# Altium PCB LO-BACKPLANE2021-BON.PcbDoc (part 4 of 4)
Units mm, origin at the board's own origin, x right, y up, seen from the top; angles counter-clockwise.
Board outline 469.9 x 101.6 mm, 4 copper layers (1, Signal Layer 1, Signal Layer 2, 4), stack 1.53 mm thick; 160 components, 92 nets, 524 pads, 8354 vias.
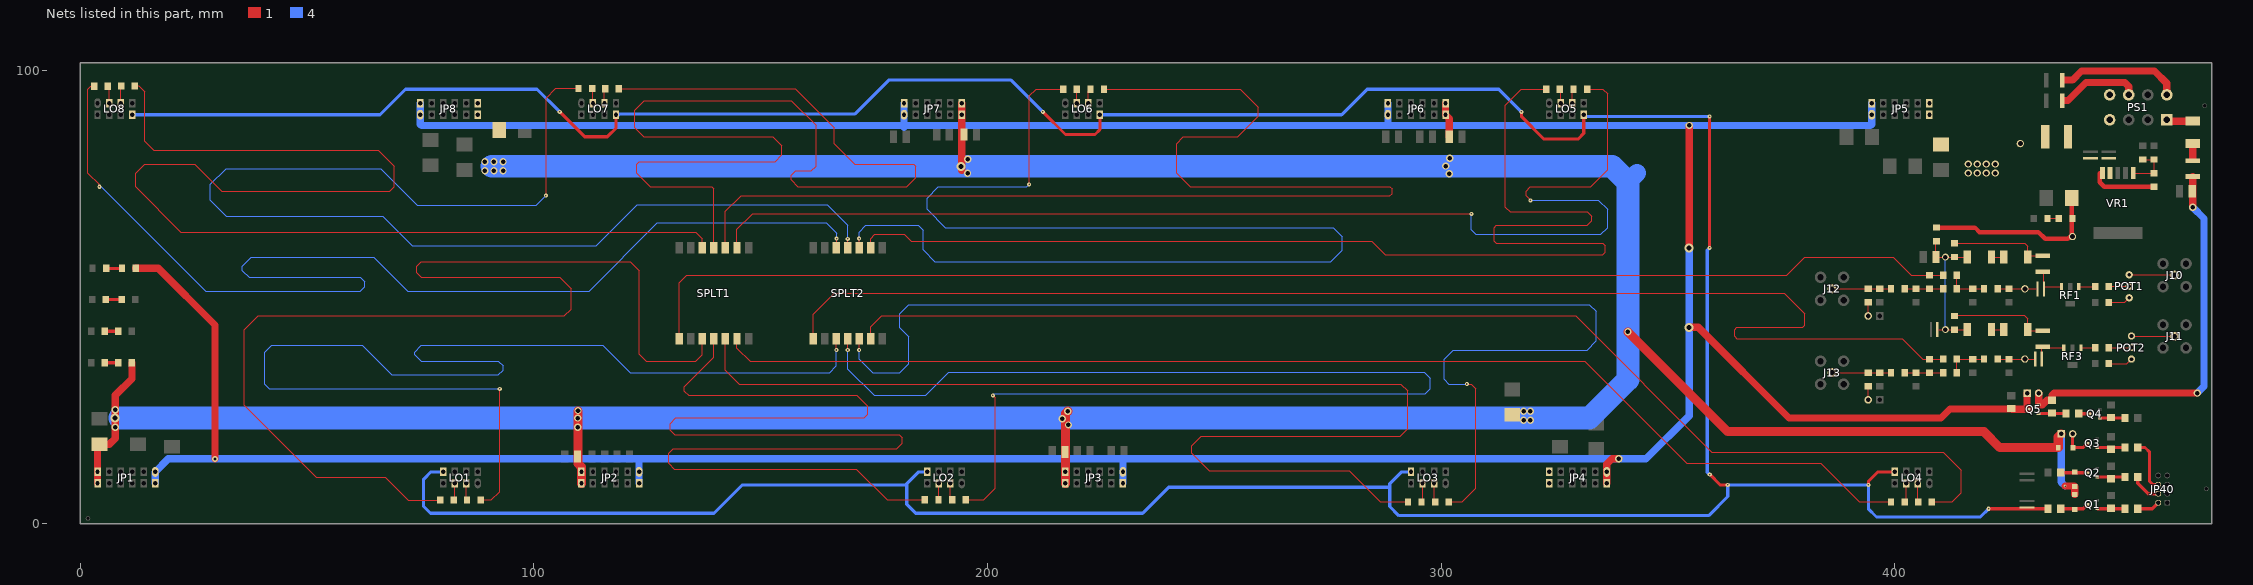
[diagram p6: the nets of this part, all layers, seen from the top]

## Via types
v1: diameter 0.9, hole 0.35, 1 to 4, 7972 vias
v2: diameter 0.7, hole 0.3, 1 to 4, 287 vias
v3: diameter 1.6, hole 1, 1 to 4, 60 vias
v4: diameter 0.762, hole 0.508, 1 to 4, 12 vias
v5: diameter 5.08, hole 3.85, 1 to 4, 12 vias
v6: diameter 2, hole 1.1, 1 to 4, 10 vias
v7: diameter 1.27, hole 0.7, 1 to 4, 1 vias

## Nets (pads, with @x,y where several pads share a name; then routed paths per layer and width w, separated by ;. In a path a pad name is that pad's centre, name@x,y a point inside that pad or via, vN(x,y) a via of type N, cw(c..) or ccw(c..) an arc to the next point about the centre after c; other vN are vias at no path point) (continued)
HFGAIN1: JP40.4 R72.1 | length 6.8
  1 w0.7: R72.1@453.6,10.3 453.6,8.9 455.88,6.62 JP40.4@458.105,6.62
I1: LO1.5 R18.2 | length 3.7
  1 w0.185: R18.2@82.369,5.23 82.55,5.411 LO1.5@82.55,8.89
I2: LO2.5 R17.2 | length 3.6
  1 w0.185: R17.2@189.2,5.3 189.23,5.33 LO2.5@189.23,8.89
I3: LO3.5 R16.2 | length 4.2
  1 w0.185: R16.2@295.7,4.8 295.91,5.01 LO3.5@295.91,8.89
I4: LO4.5 R15.2 | length 4.3
  1 w0.185: R15.2@402.2,4.8 402.59,5.19 LO4.5@402.59,8.89
I5: LO5.5 R14.2 | length 3.2
  1 w0.185: LO5.5@328.93,92.71 328.93,95.53 R14.2@329.2,95.8
I6: LO6.5 R13.2 | length 3.3
  1 w0.185: LO6.5@222.25,92.71 222.25,95.35 R13.2@222.7,95.8
I7: LO7.5 R12.2 | length 3.2
  1 w0.185: LO7.5@115.57,92.71 115.57,95.707 R12.2@115.744,95.881
I8: LO8.5 R11.2 | length 3.9
  1 w0.185: LO8.5@8.89,92.71 8.89,96.413 R11.2@9.004,96.527
I-BUS: C2.1 R20.1 R22.1 TP1.1 | length 8.5
  1 w0.185: R22.1@422.7,51.8 431.2,51.8
LFGAIN: C7.1 L1.1 LO1.8 LO2.8 LO3.8 LO4.8 LO5.8 LO6.8 LO7.8 LO8.8 | length 882.4
  1 w0.7: v1(105.7,90.8) 111.2,85.3 116.2,85.3 118.11,87.21 LO7.8@118.11,90.17 ; v1(212.2,90.8) 217.2,85.8 223.7,85.8 224.79,86.89 LO6.8@224.79,90.17 ; v1(317.7,90.8) 317.7,89.8 322.7,84.8 330.2,84.8 331.47,86.07 LO5.8@331.47,90.17 ; v1@359.199,10.877 361.526,8.55 v1(363.2,8.55) ; v1(359.2,60.8) v1(359.2,89.8) ; v1(394.2,8.55) 394.2,9.3 396.33,11.43 LO4.8@400.05,11.43 ; v1(420.7,3.3) L1.1@433.8,3.3
  4 w0.7: LO8.8@11.43,90.17 66.07,90.17 71.7,95.8 100.7,95.8 v1(105.7,90.8) ; LO1.8@80.01,11.43 77.33,11.43 75.7,9.8 75.7,3.8 77.2,2.3 139.7,2.3 145.95,8.55 182.2,8.55 ; LO7.8@118.11,90.17 118.7,90.17 118.83,90.3 170.7,90.3 178.2,97.8 205.2,97.8 v1(212.2,90.8) ; LO2.8@186.69,11.43 184.83,11.43 182.2,8.8 182.2,8.55 ; LO6.8@224.79,90.17 278.07,90.17 283.7,95.8 312.7,95.8 v1(317.7,90.8) ; LO3.8@293.37,11.43 291.33,11.43 288.7,8.8 288.7,8.05 ; LO5.8@331.47,90.17 331.84,89.8 v1(359.2,89.8) ; v1(359.2,60.8) 358.7,60.3 358.7,11.349 v1(359.226,10.822) ; v1(420.7,3.3) 418.892,1.492 396.008,1.492 394.2,3.3 v1(394.2,8.55) v1(363.2,8.55) 363.2,6.014 358.986,1.8 290.7,1.8 288.7,3.8 288.7,8.05 ; 182.2,8.55 182.2,4.3 184.2,2.3 234.2,2.3 239.95,8.05 288.7,8.05
LFGAIN1: JP40.2 R70.2 | length 4.6
  1 w0.7: R70.2@454.1,3.3 456.785,3.3 JP40.2@458.105,4.62
LOI1+: J10.1 POT1.3 | length 9.9
  1 w0.185: POT1.3@451.7,54.88 J10.1@461.62,54.88
LOI2: C1.2 POT1.2 | length 4.5
  1 w0.185: C1.2@447.2,52.3 447.24,52.34 POT1.2@451.7,52.34
LOI3: C1.1 RF1.1 | length 3.6
  1 w0.185: RF1.1@440.605,52.3 C1.1@444.2,52.3
LOI4: C2.2 L2.1 RF1.3 | length 6.9
  1 w0.185: L2.1@432.9,55.3 432.9,52.3 RF1.3@436.795,52.3
LOQ1+: J11.1 POT2.3 | length 9.5
  1 w0.185: POT2.3@452.2,41.38 452.28,41.3 J11.1@461.7,41.3
LOQ2: C3.2 POT2.2 | length 5
  1 w0.185: C3.2@447.2,38.8 447.24,38.84 POT2.2@452.2,38.84
LOQ3: C3.1 RF3.1 | length 3.1
  1 w0.185: RF3.1@441.105,38.8 C3.1@444.2,38.8
LOQ4: C4.2 L4.1 RF3.3 | length 9.2
  1 w0.185: C4.2@432.45,34.8 432.45,39.05 432.95,38.8 RF3.3@437.295,38.8
LOQ6: R54.2 R55.1 | length 2.7
  1 w0.185: R54.2@421.35,42.8 R55.1@424.05,42.8
NetC5_1: C5.1 C6.1 R44.1 R54.1 R91.2 R93.1 R94.1 | length 32.8
  1 w0.185: R91.2@409.2,62.3 409.1,62.2 C5.1@409.1,58.8 v3(411.2,58.8) R93.1@413.2,58.8 R44.1@416.05,58.8 ; 409.7,42.8 v3(411.2,42.8) R94.1@413.2,42.8 R54.1@416.05,42.8
  4 w0.185: v3(411.2,42.8) v3(411.2,58.8)
NetD1_A: D1.A L1.2 Q1.3 | length 6.3
  1 w0.7: L1.2@436.6,3.3 441.589,3.3 Q1.3@442.541,4.252
NetD2_A: D2.A L21.2 Q2.3 | length 6
  1 w0.185: L21.2@436.6,11.3 L21.2@436.648,11.252
  1 w0.7: L21.2@436.648,11.252 Q2.3@442.541,11.252
NetD103_A: D103.A JP13.2 Q3.3 | length 6.6
  1 w0.185: D103.A@439.24,16.895 D103.A@439.335,16.8
  1 w0.7: D103.A@439.24,16.895 JP13.2@439.24,19.8 ; D103.A@439.335,16.8 441.589,16.8 Q3.3@442.541,17.752
NetF1_1: F1.1 L13.2 | length 3.6
  1 w1.6: L13.2@465.7,80.3 F1.1@465.7,83.85
NetJ12_1: J12.1 R7.1 R61.1 R62.2 | length 13
  1 w0.185: J12.1@386.2,51.8 R7.1@394.2,51.8 R61.1@396.7,51.8 R62.2@399.2,51.8
NetJ13_1: J13.1 R8.1 R64.1 R65.2 | length 13
  1 w0.185: J13.1@386.2,33.3 R8.1@394.2,33.3 R64.1@396.7,33.3 R65.2@399.2,33.3
NetJP10_2: JP10.2 R7.2 | length 3
  1 w0.185: JP10.2@394.16,45.8 394.2,45.84 R7.2@394.2,48.8
NetJP11_2: JP11.2 R8.2 | length 3
  1 w0.185: JP11.2@394.2,27.34 R8.2@394.2,30.3
NetJP40_6: JP40.6 R74.1 | length 11.7
  1 w0.7: R74.1@453.6,16.8 455.2,16.8 456.2,15.8 456.2,9.3 456.88,8.62 JP40.6@458.105,8.62
NetL2_2: L2.2 R45.2 R93.2 | length 22.2
  1 w0.185: R93.2@413.2,61.8 428.7,61.8 429.35,61.15 R45.2@429.35,58.8 429.6,59.05 L2.2@432.7,59.05
NetL4_2: L4.2 R55.2 R94.2 | length 22.3
  1 w0.185: R94.2@413.2,45.8 413.325,45.925 428.575,45.925 429.35,45.15 R55.2@429.35,42.8 429.6,42.55 L4.2@432.7,42.55
NetL10_2: L10.2 PS1.4 PS1.8
NetL11_2: L11.2 PS1.7 | length 18.3
  1 w1.6: L11.2@437.2,93.3 438.2,93.3 442.2,97.3 450.7,97.3 451.6,96.4 PS1.7@451.6,94.55
NetL12_2: L12.2 PS1.5 | length 27.3
  1 w1.6: L12.2@437.2,97.8 439.2,97.8 441.2,99.8 457.3,99.8 460,97.1 PS1.5@460,94.55
NetLED1_A: LED1.A R92.2 | length 2.5
  1 w0.185: LED1.A@433.7,67.3 R92.2@436.2,67.3
NetLED80_A: LED80.A R80.1 | length 3
  1 w0.7: LED80.A@5.386,35.498 R80.1@8.386,35.498
NetLED81_A: LED81.A R81.1 | length 3
  1 w0.7: LED81.A@5.386,42.428 R81.1@8.386,42.428
NetLED82_K: LED82.K R82.1 | length 3.5
  1 w0.7: LED82.K@5.631,49.411 R82.1@9.131,49.411
NetLED83_A: LED83.A R83.1 | length 3.5
  1 w0.7: LED83.A@5.7,56.3 R83.1@9.2,56.3
NetPOT1_1: POT1.1 R42.1 | length 4.9
  1 w0.185: R42.1@447.2,48.8 450.7,48.8 POT1.1@451.7,49.8
NetPOT2_1: POT2.1 R52.1 | length 5.4
  1 w0.185: R52.1@447.2,35.3 451.2,35.3 POT2.1@452.2,36.3
NetQ3_1: Q3.1 R74.2 R75.1 | length 6.1
  1 w0.7: Q3.1@444.7,16.8 R74.2@450.8,16.8
NetQ4_1: Q4.1 R58.2 R59.1 | length 5.6
  1 w0.7: Q4.1@445.2,23.3 R58.2@450.8,23.3
NetQ4_3: Q4.3 R57.2 | length 2.5
  1 w0.185: R57.2@440.6,24.3 R57.2@440.648,24.252
  1 w0.7: R57.2@440.648,24.252 Q4.3@443.041,24.252
NetQ5_1: Q5.1 R56.2 R57.1 | length 6.1
  1 w0.7: Q5.1@431.7,24.3 R57.1@437.8,24.3
NetR1_1: R1.1 R2.1 R21.1 R22.2 | length 9
  1 w0.185: R1.1@413.7,54.8 R2.1@413.7,51.8 R22.2@419.7,51.8
NetR1_2: R1.2 R3.1 SPLT1.1 | length 295
  1 w0.185: SPLT1.1@132.08,40.765 132.08,53.18 133.7,54.8 376.2,54.8 380.2,58.8 399.7,58.8 403.7,54.8 R1.2@410.7,54.8
NetR2_2: R2.2 R3.2 R60.1 R62.1 | length 8.5
  1 w0.185: R62.1@402.2,51.8 R60.1@404.7,51.8 R3.2@407.7,51.8 R2.2@410.7,51.8
NetR4_1: R4.1 R5.1 R24.1 R25.2 | length 9
  1 w0.185: R5.1@413.7,33.3 R4.1@413.7,36.3 R24.1@417.2,36.3 R25.2@419.7,36.3
NetR4_2: R4.2 R6.1 SPLT2.1 | length 295.8
  1 w0.185: SPLT2.1@161.58,40.765 161.58,46.18 166.2,50.8 375.7,50.8 380.2,46.3 380.2,43.8 379.7,43.3 365.2,43.3 364.7,42.8 364.7,41.3 365.2,40.8 401.7,40.8 406.2,36.3 R6.1@407.7,36.3 R4.2@410.7,36.3
NetR5_2: R5.2 R6.2 R63.1 R65.1 | length 8.5
  1 w0.185: R65.1@402.2,33.3 R63.1@404.7,33.3 R5.2@410.7,33.3
NetR11_1: R11.1 SPLT1.12 | length 270.8
  1 w0.185: R11.1@12.004,96.527 12.838,96.527 14.178,95.186 14.178,84.322 16.2,82.3 65.7,82.3 69.2,78.8 69.2,74.3 68.2,73.3 31.2,73.3 25.2,79.3 14.2,79.3 12.2,77.3 12.2,74.3 22.2,64.3 135.7,64.3 137.16,62.84 SPLT1.12@137.16,60.835
NetR12_1: R12.1 SPLT1.11 | length 271.8
  1 w0.185: R12.1@118.744,95.881 157.619,95.881 166.2,87.3 166.2,83.8 170.7,79.3 183.7,79.3 184.2,78.8 184.2,76.3 182.2,74.3 158.2,74.3 156.7,75.8 156.7,76.8 157.7,77.8 161.2,77.8 162.2,78.8 162.2,87.8 156.7,93.3 124.328,93.3 122.2,91.172 122.2,87.3 124.2,85.3 152.7,85.3 154.7,83.3 154.7,81.3 153.2,79.8 123.2,79.8 122.7,79.3 122.7,77.3 125.7,74.3 139.2,74.3 139.7,73.8 SPLT1.11@139.7,60.835
NetR13_1: R13.1 SPLT1.10 | length 271.2
  1 w0.185: SPLT1.10@142.24,60.835 142.24,68.84 145.7,72.3 288.7,72.3 289.2,72.8 289.2,73.8 288.7,74.3 244.7,74.3 241.7,77.3 241.7,83.8 243.2,85.3 255.2,85.3 259.7,89.8 259.7,91.8 255.7,95.8 R13.1@225.7,95.8
NetR14_1: R14.1 SPLT1.9 | length 267.8
  1 w0.185: SPLT1.9@144.78,60.835 144.78,64.88 148.2,68.3 v1(306.7,68.3) ; v1@319.747,71.347 318.738,72.357 318.738,73.338 319.7,74.3 333.01,74.3 336.7,77.99 336.7,94.8 335.7,95.8 R14.1@332.2,95.8
  4 w0.185: v1(306.7,68.3) 306.7,64.8 307.7,63.8 335.2,63.8 336.7,65.3 336.7,69.3 334.7,71.3 v1(319.7,71.3)
NetR15_1: R15.1 SPLT1.6 | length 270.5
  1 w0.185: SPLT1.6@144.78,40.765 144.78,38.72 147.7,35.8 331.7,35.8 354.2,13.3 383.7,13.3 392.2,4.8 R15.1@399.2,4.8
NetR16_1: R16.1 SPLT1.5 | length 270.5
  1 w0.185: SPLT1.5@142.24,40.765 142.24,33.8 145.28,30.76 291.142,30.76 292.628,29.273 292.628,20.928 291.005,19.305 247.14,19.305 245.027,17.192 245.027,15.516 248.867,11.675 279.764,11.675 286.639,4.8 R16.1@292.7,4.8
NetR17_1: R17.1 SPLT1.4 | length 271.2
  1 w0.185: SPLT1.4@139.7,40.765 139.7,36.676 133.178,30.154 133.178,29.229 134.107,28.3 171.192,28.3 173.553,25.939 173.553,24.09 172.792,23.329 131.329,23.329 130.051,22.051 130.051,20.637 131.03,19.659 180.595,19.659 181.248,19.006 181.248,17.755 180.051,16.559 130.731,16.559 129.697,15.526 129.697,13.351 131.002,12.046 171.106,12.046 177.852,5.3 R17.1@186.2,5.3
NetR18_1: R18.1 SPLT1.3 | length 271
  1 w0.185: R18.1@79.096,5.23 72.27,5.23 67.2,10.3 51.997,10.3 36.167,26.13 36.167,42.769 39.198,45.8 106.7,45.8 108.2,47.3 108.2,51.8 105.7,54.3 75.2,54.3 74.2,55.3 74.2,56.8 75.2,57.8 121.2,57.8 123.229,55.771 123.229,37.329 124.758,35.8 135.7,35.8 137.16,37.26 SPLT1.3@137.16,40.765
NetR31_1: R31.1 SPLT2.12 | length 267.9
  1 w0.185: 1.664,78.3 1.664,95.782 2.31,96.428 R31.1@3.045,96.428 ; 1.7,78.3 1.7,77.3 4.2,74.8 v1@4.2,74.378 ; SPLT2.12@166.728,60.903 v1(166.728,62.859)
  4 w0.185: v1(4.2,74.3) 4.624,74.3 27.624,51.3 61.7,51.3 62.7,52.3 62.7,53.3 61.7,54.3 37.2,54.3 35.7,55.8 35.7,56.8 37.7,58.8 64.7,58.8 72.2,51.3 112.2,51.3 127.235,66.335 164.469,66.335 166.728,64.075 v1(166.728,62.859)
NetR32_1: R32.1 SPLT2.11 | length 267.8
  1 w0.185: v1@102.7,72.351 102.7,93.8 104.856,95.956 R32.1@109.835,95.956 ; SPLT2.11@169.2,60.835 v1(169.2,62.8)
  4 w0.185: v1(102.644,72.351) 100.524,70.23 74.27,70.23 66.2,78.3 32.2,78.3 28.7,74.8 28.7,71.3 32.2,67.8 66.7,67.8 73.188,61.312 113.765,61.312 122.753,70.3 164.7,70.3 169.2,65.8 v1(169.2,62.8)
NetR33_1: R33.1 SPLT2.10 | length 268.8
  1 w0.185: v1(171.7,62.84) 171.7,63.3 ; SPLT2.10@171.74,60.835 v1@171.74,62.84 ; v1(209.2,74.8) 209.2,94.3 210.7,95.8 R33.1@216.7,95.8
  4 w0.185: v1@171.7,62.8 v1(171.7,62.84) 171.7,64.3 173.2,65.8 184.753,65.8 185.815,64.738 185.815,60.388 188.403,57.8 275.7,57.8 278.2,60.3 278.2,63.3 276.2,65.3 190.7,65.3 186.7,69.3 186.7,71.8 189.2,74.3 208.7,74.3 v1(209.2,74.8)
NetR34_1: R34.1 SPLT2.9 | length 271.7
  1 w0.185: SPLT2.9@174.28,60.835 174.28,62.88 175.2,63.8 181.7,63.8 183.2,62.3 284.7,62.3 287.707,59.293 335.693,59.293 336.2,59.8 336.2,61.3 335.7,61.8 312.2,61.8 311.7,62.3 311.7,65.3 312.2,65.8 332.2,65.8 333.2,66.8 333.2,67.8 332.2,68.8 315.2,68.8 314.2,69.8 314.2,92.3 317.7,95.8 R34.1@323.2,95.8
NetR35_1: R35.1 SPLT2.6 | length 270.4
  1 w0.185: SPLT2.6@174.28,40.765 174.28,43.38 176.7,45.8 329.7,45.8 359.7,15.8 410.7,15.8 414.7,11.8 414.7,6.8 412.7,4.8 R35.1@408.2,4.8
NetR36_1: R36.1 SPLT2.5 | length 268
  1 w0.185: v1(171.7,38.3) 171.74,38.34 SPLT2.5@171.74,40.765 ; SPLT2.5@171.7,40.34 SPLT2.5@171.7,40.765 ; R36.1@301.7,4.8 304.7,4.8 307.7,7.8 307.7,29.8 306.7,30.8 v1(305.7,30.8)
  4 w0.185: v1(171.7,38.3) 171.7,36.3 174.7,33.3 180.7,33.3 182.7,35.3 182.7,41.217 180.7,43.217 180.7,46.3 182.7,48.3 332.7,48.3 334.2,46.8 334.2,40.3 332.2,38.3 302.7,38.3 300.7,36.3 300.7,31.8 301.7,30.8 v1(305.7,30.8)
NetR37_1: R37.1 SPLT2.4 | length 267.8
  1 w0.185: v1(169.2,38.3) SPLT2.4@169.2,40.765 ; R37.1@195.2,5.3 199.2,5.3 201.7,7.8 201.7,27.8 v1(201.2,28.3)
  4 w0.185: v1(169.2,38.3) 169.2,34.099 174.999,28.3 186.354,28.3 191.471,33.416 296.311,33.416 297.616,32.111 297.616,29.773 296.474,28.631 201.531,28.631 v1(201.2,28.3)
NetR38_1: R38.1 SPLT2.3 | length 267.4
  1 w0.185: R38.1@88.651,5.243 90.64,5.243 92.44,7.043 v1@92.44,29.719 ; SPLT2.3@166.66,40.765 166.7,40.725 v1(166.7,38.3)
  4 w0.185: 59.2,29.773 92.421,29.773 v1(92.476,29.719) ; 59.2,29.8 41.7,29.8 40.7,30.8 40.7,37.8 42.2,39.3 62.2,39.3 68.7,32.8 92.2,32.8 93.2,33.8 93.2,34.8 92.2,35.8 79.2,35.8 75.2,35.8 73.7,37.3 73.7,37.8 75.2,39.3 115.2,39.3 121.2,33.3 165.2,33.3 166.7,34.8 v1(166.7,38.3)
NetR44_2: R44.2 R45.1 | length 2.7
  1 w0.185: R44.2@421.35,58.8 R45.1@424.05,58.8
NetR95_2: R95.2 R96.1 R97.1 VR1.1 | length 10.1
  1 w0.185: VR1.1@452.604,77.3 R95.2@457.2,77.3 R96.1@457.2,80.3 R97.1@454.7,80.3
PANT1: F1.2 PS1.1 | length 5.8
  1 w0.185: PS1.1@460,89.05 PS1.1@460.3,88.75
  1 w1.6: PS1.1@460.3,88.75 F1.2@465.7,88.75
PANT2: C28.1 JP12.2 L13.1 Q5.2 R56.1 | length 88.7
  1 w1.6: JP12.2@431.74,28.8 431.74,26.245 Q5.2@431.7,26.205 432.605,26.205 433.6,27.2 R56.1@434.7,27.2 434.7,28.3 435.2,28.8 v3(466.7,28.8) ; v3(465.7,69.8) L13.1@465.7,76.55
  4 w1.6: v3(465.7,69.8) 468.2,67.3 468.2,30.3 v3(466.7,28.8)
PANT3: C13.1 JP1.1 JP1.2 JP2.1 JP2.2 JP3.1 JP3.2 JP4.1 JP4.2 JP5.1 JP5.2 JP6.1 JP6.2 JP7.1 JP7.2 JP8.1 JP8.2 JP12.1 Q5.3 R83.2 | length 908.2
  1 w1.6: R83.2@12.2,56.3 17.2,56.3 29.7,43.8 v7(29.7,14.3) ; JP4.2@336.55,8.89 JP4.1@336.55,11.43 336.55,13.15 337.7,14.3 v3(339.2,14.3) ; v6(354.7,43.3) 356.7,43.3 376.7,23.3 410.2,23.3 412.2,25.3 425.6,25.3 C13.1@425.7,25.4 425.848,25.252 Q5.3@429.541,25.252 429.2,25.594 JP12.1@429.2,28.8 ; v6(354.7,60.8) v3(354.7,87.8)
  4 w1.6: JP1.2@16.51,8.89 JP1.1@16.51,11.43 19.38,14.3 v7(29.7,14.3) 123.2,14.3 ; JP8.2@74.93,92.71 JP8.1@74.93,90.17 74.93,88.07 75.2,87.8 181.61,87.8 ; JP2.2@123.19,8.89 JP2.1@123.19,11.43 123.19,14.29 123.2,14.3 ; 181.61,87.39 182.02,87.8 ; JP7.2@181.61,92.71 JP7.1@181.61,90.17 181.61,87.8 ; JP3.2@229.87,8.89 JP3.1@229.87,11.43 229.87,13.97 230.2,14.3 ; JP6.2@288.29,92.71 JP6.1@288.29,90.17 288.29,88.21 287.88,87.8 ; v6(354.7,60.8) v6(354.7,43.3) 354.7,23.8 345.2,14.3 v3(339.2,14.3) 230.2,14.3 ; JP5.2@394.97,92.71 JP5.1@394.97,90.17 394.97,88.07 394.7,87.8 287.88,87.8 ; 123.2,14.3 230.2,14.3 ; 181.61,87.8 182.02,87.8 ; 182.02,87.8 287.88,87.8
Q1: LO1.3 R38.2 | length 3.7
  1 w0.185: LO1.3@85.09,8.89 85.09,5.419 R38.2@85.254,5.255
Q1B: Q1.1 R70.1 R71.1 | length 6.1
  1 w0.7: Q1.1@444.7,3.3 R70.1@450.8,3.3
Q2: LO2.3 R37.2 | length 3.8
  1 w0.185: LO2.3@191.77,8.89 191.77,5.73 R37.2@192.2,5.3
Q2B: Q2.1 R72.2 R73.1 | length 5.6
  1 w0.7: Q2.1@444.7,10.3 R72.2@450.3,10.3
Q3: LO3.3 R36.2 | length 4.2
  1 w0.185: LO3.3@298.45,8.89 298.45,5.05 R36.2@298.7,4.8
Q4: LO4.3 R35.2 | length 4.1
  1 w0.185: LO4.3@405.13,8.89 405.13,4.87 R35.2@405.2,4.8
Q5: LO5.3 R34.2 | length 3.2
  1 w0.185: R34.2@326.2,95.8 326.39,95.61 LO5.3@326.39,92.71
Q6: LO6.3 R33.2 | length 3.1
  1 w0.185: LO6.3@219.71,92.71 R33.2@219.71,95.79
Q7: LO7.3 R32.2 | length 3.3
  1 w0.185: R32.2@112.835,95.956 113.03,95.761 LO7.3@113.03,92.71
Q8: LO8.3 R31.2 | length 3.8
  1 w0.185: R31.2@6.045,96.428 6.35,96.122 LO8.3@6.35,92.71
Q-BUS: C4.1 R23.1 R25.1 TP2.1 | length 8
  1 w0.185: R25.1@422.7,36.3 TP2.1@428.7,36.3 430.7,36.3
V12: C11.1 C12.1 C20.+ C21.+ C22.+ C23.+ C24.1 C25.1 C26.1 C27.1 D1.K D2.K D103.K JP1.11 JP1.12 JP2.11 JP2.12 JP3.11 JP3.12 JP4.11 JP4.12 JP5.11 JP5.12 JP6.11 JP6.12 JP7.11 JP7.12 JP8.11 JP8.12 JP13.1 L10.1 R80.2 TP10.1 VR1.4 | length 844.7
  1 w0.7: v6(7.7,23.3) v6@7.7,23.8
  1 w1.6: JP1.12@3.81,8.89 JP1.11@3.81,11.43 3.81,17.104 C21.+@4.2,17.494 6.394,17.494 7.7,18.8 v6(7.7,23.3) ; v6@7.7,23.8 7.7,28.3 11.386,31.986 R80.2@11.386,35.498 ; v6@194.31,77.91 JP7.11@194.31,90.17 JP7.12@194.31,92.71 ; JP6.12@300.99,92.71 JP6.11@300.99,90.17 301.8,89.36 C24.1@301.8,85.3 ; v2(437.575,8.3) 439.565,8.3 D2.K@439.7,8.165 D1.K@439.7,6.435
  1 w2: v3@109.7,24.8 109.7,13.3 110.49,12.51 JP2.11@110.49,11.43 JP2.12@110.49,8.89 ; JP3.12@217.17,8.89 JP3.11@217.17,11.43 217.17,24.27 v3(217.7,24.8) ; v3(341.2,42.3) 363.2,20.3 419.7,20.3 423.2,16.8 D103.K@436.065,16.8 436.065,19.165 JP13.1@436.7,19.8
  4 w1.6: JP13.1@436.7,19.8 436.7,9.175 v2(437.575,8.3)
  4 w4: 341.2,75.3 343.2,77.3
  4 w5: 8.7,23.3 v3(109.7,23.3) 332.7,23.3 341.2,31.8 v3(341.2,42.3) 341.2,75.3 337.7,78.8 v6(194.2,78.8) 90.7,78.8
  other v3: 7.728,21.29 109.7,21.3 217.858,21.779 318.2,22.8 319.7,22.8 216.471,23.152 318.2,24.8 319.7,24.8 109.727,24.96 7.728,25.151 301.817,77.15 195.603,77.286 416.2,77.3 418.2,77.3 420.2,77.3 422.2,77.3 89.2,77.8 91.2,77.8 93.2,77.8 301.029,78.849 416.2,79.3 418.2,79.3 420.2,79.3 422.2,79.3 89.2,79.8 91.2,79.8 93.2,79.8 195.671,80.331 301.926,80.562
VCC: C14.+ R91.1 R92.1 R95.1 TP9.1 VR1.5 | length 53.9
  1 w1: R91.1@409.2,65.3 417.7,65.3 418.7,64.3 431.7,64.3 433.2,62.8 438.2,62.8 TP9.1@439.006,63.606 ; TP9.1@439.006,63.494 TP9.1@439.006,63.606 ; C14.+@439.006,71.8 TP9.1@439.006,63.606 ; 445.2,77.3 445.2,75.3 446.2,74.3 R95.1@457.2,74.3
copper on no net:
  other v5: 380.365,3.175

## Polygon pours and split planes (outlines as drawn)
GND on 1 "GND_L01_P002" (solid, remove dead copper, pour order 2): 470.575,102.675 470.575,18.8 465.325,18.8 465.2,18.675 465.2,8.8 470.45,3.55 470.45,-0.2 469.325,-1.325 6.45,-1.325 -1.55,6.675 -1.55,103.3 -1.675,103.3 -1.8,103.425
GND on Signal Layer 2 "GND_L03_P003" (solid, remove dead copper, pour order 3): 470.575,102.675 470.575,18.8 465.325,18.8 465.2,18.675 465.2,8.8 470.45,3.55 470.45,-0.2 469.325,-1.325 6.45,-1.325 -1.55,6.675 -1.55,103.3 -1.675,103.3 -1.8,103.425
GND on Signal Layer 1 "GND_L02_P004" (solid, remove dead copper, pour order 4): 470.575,102.675 470.575,18.8 465.325,18.8 465.2,18.675 465.2,8.8 470.45,3.55 470.45,-0.2 469.325,-1.325 6.45,-1.325 -1.55,6.675 -1.55,103.3 -1.675,103.3 -1.8,103.425
GND on 4 "GND_L04_P001" (solid, remove dead copper, pour order 1): 470.575,102.675 470.575,18.8 465.325,18.8 465.2,18.675 465.2,8.8 470.45,3.55 470.45,-0.2 469.325,-1.325 6.45,-1.325 -1.55,6.675 -1.55,103.3 -1.675,103.3 -1.8,103.425

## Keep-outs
Keep-Out Layer:
  the board outline again, w0.1

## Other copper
1:
  rectangle net V12: 192.803,76.293 196.569,81.282
  rectangle net V12: 314.2,7.3 324.7,13.3
  rectangle net V12: 314.2,7.3 320.7,25.8
  rectangle net V12: 300.2,76.3 302.7,93.8
  rectangle net V12: 215.7,20.8 218.7,25.8
  rectangle net GND: 443.7,60.425 454.7,63.925
  region net NetL10_2: 443.7,95.8 438.7,90.8 437.7,90.8 435.7,88.8 435.7,82.8 436.7,81.8 439.7,81.8 445.2,87.3 448.2,87.3 449.2,88.3 449.2,95.3 448.7,95.8
  region net V12: 434.2,88.8 434.7,88.3 434.7,81.8 435.2,81.3 448.7,81.3 449.2,80.8 449.2,80.3 448.2,79.3 448.2,75.8 446.7,75.8 446.7,78.8 446.2,79.3 439.7,79.3 436.2,75.8 415.7,75.8 414.2,77.3 414.2,78.8 412.2,80.8 407.2,80.8 406.7,81.3 406.7,93.8 407.7,94.8 411.2,94.8 415.7,90.3 415.7,88.3 416.7,87.3 425.7,87.3 426.7,88.3 426.7,89.8 427.2,90.3 432.7,90.3
  region net VCC: 446.2,78.3 445.7,78.8 440.2,78.8 436.7,75.3 436.7,69.8 437.7,68.8 440.7,68.8 441.7,69.8 446.2,74.3
  region net V12: 86.7,93.8 86.7,88.8 88.2,87.3 88.2,75.8 94.2,75.8 94.2,92.8 93.2,93.8
  text "1" at 468.696,9.054 h1.52 r90
Signal Layer 1:
  text "2" at 468.446,10.804 h1.52 r90
Signal Layer 2:
  text "3" at 468.196,13.429 h1.52 r90
4:
  rectangle net -15VBUS: 429.2,96.8 432.7,98.8
  rectangle net +15VBUS: 429.2,92.3 432.7,94.3
  rectangle net V12: 314.2,21.8 320.7,25.8
  rectangle net V12: 414.7,76.3 424.2,80.3
  region net V12: 338.7,80.3 338.7,68.3 418.7,68.3 424.2,73.8 424.2,80.3
  text "4" at 468.071,16.179 h1.52 r90

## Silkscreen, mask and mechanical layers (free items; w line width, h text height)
Top Overlay:
  text "V12" at 88.149,94.976 h2 r90
  text "+15V" at 85.601,94.355 h2 r90
  text "PANT3" at 75.199,94.243 h2 r90
  text "GND" at 82.893,94.211 h2 r90
  text "-15V" at 77.763,94.195 h2 r90
  text "GND" at 80.344,94.116 h2 r90
  text "7" at 154.2,81.3 h10.16 r180
  text "V12" at 426.2,80.8 h2
  text "5" at 363.2,74.8 h10.16 r180
  text "8" at 48.895,74.549 h10.16 r180
  text "6" at 258.7,74.3 h10.16 r180
  text "VCC" at 425.2,66.8 h2
  text "VCC" at 437.2,59.8 h2
  text "PANT3" at 2.2,59.3 h2
  text "-15V" at 1.7,52.3 h2
  text "University of Hawaii SOEST" at 95.7,48.8 h1.27 r180
  text "1" at 48.387,46.228 h10.16 r180
  text "+15V" at 1.863,45.429 h2
  text "3" at 258.2,43.8 h10.16 r180
  text "Radio Oceanography Laboratory" at 106.2,43.3 h1.91 r180
  text "V12" at 2.558,38.476 h2
  text "4" at 358.9,36.516 h10.16 r180
  text "2" at 138.7,30.8 h10.16 r180
  text "LO-BACKPLANE-2021" at 235.325,22.342 h5
  text "1" at 463.2,4.8 h2
Mechanical 1:
  lines w0.203: 167.005,3.175 167.005,98.425 ; 380.365,0 380.365,101.6 ; 472.44,0 473.71,0 ; 472.44,3.175 473.71,3.175 ; 472.593,-1.445 473.075,0 ; 472.593,4.62 473.075,3.175 ; 473.075,-1.905 473.075,0 ; 473.075,5.08 473.075,3.175 ; 473.557,-1.445 473.075,0 ; 473.557,4.62 473.075,3.175 ; 523.24,0 524.51,0 ; 523.24,3.175 524.51,3.175 ; 523.875,0 524.357,-1.445 ; 523.875,3.175 524.357,4.62
  lines w0.305: -50.8,50.8 474.726,50.8 ; 273.685,0 273.685,101.6
  lines w0.508: -58.42,-64.77 -50.165,-64.77
  text "-15V" at 76.835,109.855 h2.03 r270
  text "+15V" at 84.455,109.855 h2.03 r270
  text "-15V" at 183.515,109.855 h2.03 r270
  text "+15V" at 191.135,109.855 h2.03 r270
  text "-15V" at 290.195,109.855 h2.03 r270
  text "+15V" at 297.815,109.855 h2.03 r270
  text "Ant" at 74.295,108.585 h2.03 r270
  text "GND" at 79.375,108.585 h2.03 r270
  text "GND" at 81.915,108.585 h2.03 r270
  text "V12" at 86.995,108.585 h2.03 r270
  text "Ant" at 180.975,108.585 h2.03 r270
  text "GND" at 186.055,108.585 h2.03 r270
  text "GND" at 188.595,108.585 h2.03 r270
  text "V12" at 193.675,108.585 h2.03 r270
  text "Ant" at 287.655,108.585 h2.03 r270
  text "GND" at 292.735,108.585 h2.03 r270
  text "GND" at 295.275,108.585 h2.03 r270
  text "V12" at 300.355,108.585 h2.03 r270
  text "Q I" at 38.1,106.68 h4.06
  text "Q I" at 147.32,106.68 h4.06
  text "LO POWER LED" at 431.165,103.505 h1.52
  text "240-2433-1-ND ferrite" at 477.52,86.995 h1.52 r270
  text "L2220" at 457.2,75.565 h1.52
  text "13.250" at 391.16,55.245 h1.52
  text "13.191" at 391.16,48.895 h1.52
  text "6.2x10.2mm" at 453.39,-1.905 h1.02
  text "125mil" at 472.44,-1.905 h1.27 r270
  text "I  Q" at 290.83,-5.715 h3.81
  text "I  Q" at 396.875,-5.715 h3.81
  text "V12" at 111.125,-6.985 h2.03 r90
  text "GND" at 116.205,-6.985 h2.03 r90
  text "GND" at 118.745,-6.985 h2.03 r90
  text "Ant" at 123.825,-6.985 h2.03 r90
  text "V12" at 217.805,-6.985 h2.03 r90
  text "GND" at 222.885,-6.985 h2.03 r90
  text "GND" at 225.425,-6.985 h2.03 r90
  text "Ant" at 230.505,-6.985 h2.03 r90
  text "V12" at 324.485,-6.985 h2.03 r90
  text "GND" at 329.565,-6.985 h2.03 r90
  text "GND" at 332.105,-6.985 h2.03 r90
  text "Ant" at 337.185,-6.985 h2.03 r90
  text "+15V" at 113.665,-8.255 h2.03 r90
  text "-15V" at 121.285,-8.255 h2.03 r90
  text "+15V" at 220.345,-8.255 h2.03 r90
  text "-15V" at 227.965,-8.255 h2.03 r90
  text "+15V" at 327.025,-8.255 h2.03 r90
  text "-15V" at 334.645,-8.255 h2.03 r90
Mechanical 4:
  lines w0.203: 24.765,3.175 26.035,3.175 ; 24.765,98.425 26.035,98.425 ; 25.4,2.54 25.4,3.81 ; 25.4,97.79 25.4,99.06 ; 59.69,3.175 60.96,3.175 ; 59.69,98.425 60.96,98.425 ; 60.325,2.54 60.325,3.81 ; 60.325,97.79 60.325,99.06 ; 166.37,3.175 167.64,3.175 ; 166.37,98.425 167.64,98.425 ; 167.005,2.54 167.005,3.81 ; 167.005,97.79 167.005,99.06 ; 273.05,3.175 274.32,3.175 ; 273.05,98.425 274.32,98.425 ; 273.685,2.54 273.685,3.81 ; 273.685,97.79 273.685,99.06 ; 379.73,3.175 381,3.175 ; 379.73,98.425 381,98.425 ; 380.365,2.54 380.365,3.81 ; 380.365,97.79 380.365,99.06 ; 461.01,31.115 462.28,31.115 ; 461.01,48.26 462.28,48.26 ; 461.645,30.48 461.645,31.75 ; 461.645,47.625 461.645,48.895 ; 466.09,98.425 467.36,98.425 ; 466.725,97.79 466.725,99.06
  lines w0.254: 120.325,94.425 165.825,48.925 ; 122.075,92.675 165.825,48.925 ; 123.45,91.3 145.325,69.425 ; 139.325,75.425 145.325,69.425 ; 140.575,74.175 145.325,69.425 ; 146.575,68.175 158.825,55.925 ; 160.825,53.925 165.825,48.925 ; 164.325,50.425 165.825,48.925 ; 255.2,94.675 245.794,85.269 245.794,84.706 236.387,75.3 236.387,73.3 236.387,71.3 236.387,69.3 236.387,67.3 236.387,66.3 236.387,64.3 236.387,63.3 236.387,61.3 236.387,58.8 236.387,56.8 236.387,55.8 236.387,53.8 236.387,51.8 236.387,49.8 236.387,46.8 236.387,45.862 175.484,45.862 172.422,48.925 165.825,48.925 ; 145.325,69.425 165.825,48.925
  lines w0.305: 24.765,3.175 26.035,3.175 ; 24.765,98.425 26.035,98.425 ; 25.4,2.54 25.4,3.81 ; 25.4,97.79 25.4,99.06
  lines w0.635: -55.88,101.6 173.355,101.6 ; -54.61,0 171.45,0 ; 7.62,0 7.62,101.6 ; 25.4,0 25.4,101.6 ; 60.325,0 60.325,101.6 ; 83.82,0 83.82,101.6 ; 111.76,45.085 111.76,55.245 ; 114.3,0 114.3,101.6 ; 167.005,0 167.005,101.6 ; 190.5,0 190.5,101.6 ; 224.79,45.085 224.79,55.88
  text "20500mil,2000mil" at 416.56,109.22 h4.06
  text "3000mil,1875mil" at 11.43,104.14 h1.91
  text "12775mil,1875mil" at 244.729,103.886 h4.06
  text "16975mil,1875mil" at 347.726,103.759 h4.06
  text "4375mil,1875mil" at 46.99,103.505 h4.06
  text "8575mil,1875mil" at 153.924,103.251 h4.06
  text "20375mil,1875mil" at 469.9,93.98 h1.52
  text "16.331" at 332.74,89.535 h1.52 r270
  text "16.320" at 217.17,86.995 h1.52 r270
  text "16.284" at 223.52,86.995 h1.52 r270
  text "16.316" at 322.58,86.995 h1.52 r270
  text "16.622" at 12.065,86.36 h1.52
  text "16.287" at 109.22,85.725 h1.52 r270
  text "16.287" at 118.745,85.725 h1.52 r270
  text "16.700" at 10.16,78.105 h1.52
  text "18500mil,550mil" at 415.925,60.96 h1.52
  text "18500mil,550mil" at 393.065,57.785 h4.06
  text "67 OHMS (040 > 030)" at 257.81,53.34 h2.03
  text "50 OHMS (050 > 050)" at 348.615,52.705 h2.03
  text "100 OHMS  (024 > 010)" at 132.08,50.8 h2.03
  text "18500mil,-650mil" at 415.925,29.845 h1.52
  text "18500mil,-650mil" at 389.89,27.305 h4.06
  text "16.312" at 75.565,25.4 h1.52 r270
  text "16.337" at 88.265,25.4 h1.52 r270
  text "16.300" at 292.735,25.4 h1.52 r270
  text "16.325" at 399.415,25.4 h1.52 r270
  text "16.332" at 407.035,25.4 h1.52 r270
  text "16.300" at 300.355,24.765 h1.52 r270
  text "16.312" at 183.515,18.415 h1.52 r270
  text "16.262" at 196.215,18.415 h1.52 r270
  text "21375mil,-1375mil" at 472.44,6.35 h1.52 r90
  text "3000mil,-1875mil" at 8.255,-3.81 h1.91
  text "16975mil,-1875mil" at 349.885,-6.35 h4.06
  text "8575mil,-1875mil" at 138.43,-6.985 h4.06
  text "12775mil,-1875mil" at 245.11,-6.985 h4.06
  text "4375mil,-1875mil" at 34.29,-8.89 h4.06
  text "20500mil,-2000mil" at 414.02,-10.16 h4.06
Mechanical 5:
  lines w0.127: 329.831,-81.537 329.831,-72.857 ; 368.939,-66.032 486.242,-66.032 ; 368.939,-59.207 486.242,-59.207 ; 368.939,-48.116 486.242,-48.116 ; 368.939,-43.851 486.242,-43.851 ; 368.939,-39.585 486.242,-39.585 ; 368.939,-35.319 486.242,-35.319 ; 392.314,-52.382 392.314,-31.054 ; 409.812,-72.857 409.812,-52.382 ; 450.01,-52.382 450.01,-31.054 ; 469.033,-52.382 469.033,-31.054 ; 486.242,-31.054 329.831,-31.054 ; 329.831,-72.857 329.831,-31.054 ; 329.831,-72.857 368.939,-72.857 ; 329.831,-72.857 486.242,-72.857 ; 329.831,-31.054 368.939,-31.054 ; 368.939,-72.857 368.939,-52.382 ; 368.939,-72.857 486.242,-72.857 ; 368.939,-72.857 368.939,-31.054 ; 368.939,-72.857 368.939,-31.054 ; 368.939,-52.382 486.242,-52.382 ; 368.939,-52.382 486.242,-52.382 ; 468.174,-72.857 468.174,-59.207 ; 468.174,-72.857 486.242,-72.857 ; 468.174,-72.857 468.174,-59.207 ; 468.174,-66.032 468.174,-59.207 ; 468.174,-66.032 486.242,-66.032 ; 468.174,-66.032 468.174,-59.207 ; 468.174,-59.207 486.242,-59.207 ; 468.174,-59.207 486.242,-59.207 ; 486.242,-72.857 486.242,-52.382 ; 486.242,-72.857 486.242,-59.207 ; 486.242,-66.032 486.242,-59.207
  lines w0.5: -13.875,-81.526 -13.875,128.474 486.251,128.474 486.251,-81.526 329.851,-81.526 -13.875,-81.526
  text "Radio / Oceanography / Laboratory" at 335.778,-45.644 h4
  text "Indice" at 373,-50.972 h1.76
  text "Modification" at 411.969,-50.972 h1.76
  text "Date" at 455.643,-50.972 h1.76
  text "Dessine par" at 471.198,-51.055 h1.5
  text "Edition" at 369.91,-56.984 h1.76
  text ":" at 389.849,-56.984 h1.76
  text "CARTE LO-BACKPLANE-2021" at 413.651,-57.626 h1.8
  text "Dessinateur" at 369.91,-62.995 h1.76
  text "Folio" at 469.049,-62.995 h1.8
  text ":" at 389.849,-63.016 h1.76
  text ":" at 477.518,-63.016 h1.76
  text "1/1" at 479.895,-63.392 h1.76
  text "RONVEL" at 392.917,-63.506 h1.95
  text ":" at 389.849,-69.609 h1.76
  text "Date" at 369.91,-69.66 h1.76
  text "Ind" at 469.049,-69.66 h1.95
  text "09-06-2021" at 391.951,-70.626 h1.8
Mechanical 6:
  lines w0.127: -13.82,-48.089 103.483,-48.089 ; -13.82,-43.823 103.483,-43.823 ; -13.82,-39.558 103.483,-39.558 ; -13.82,-35.292 103.483,-35.292 ; -13.82,-31.026 142.591,-31.026 ; 3.389,-52.355 3.389,-31.026 ; 22.412,-52.355 22.412,-31.026 ; 62.61,-72.83 62.61,-52.355 ; 80.108,-52.355 80.108,-31.026 ; 103.483,-66.005 -13.82,-66.005 ; 103.483,-59.18 -13.82,-59.18 ; 142.591,-81.51 142.591,-72.83 ; -13.82,-72.83 142.591,-72.83 ; -13.82,-72.83 -13.82,-59.18 ; -13.82,-72.83 4.248,-72.83 ; -13.82,-72.83 -13.82,-52.355 ; -13.82,-72.83 103.483,-72.83 ; -13.82,-66.005 -13.82,-59.18 ; -13.82,-66.005 4.248,-66.005 ; -13.82,-59.18 4.248,-59.18 ; -13.82,-59.18 4.248,-59.18 ; -13.82,-52.355 103.483,-52.355 ; -13.82,-52.355 103.483,-52.355 ; 4.248,-72.83 4.248,-59.18 ; 4.248,-72.83 4.248,-59.18 ; 4.248,-66.005 4.248,-59.18 ; 4.248,-66.005 4.248,-59.18 ; 103.483,-72.83 103.483,-31.026 ; 103.483,-72.83 103.483,-31.026 ; 103.483,-72.83 142.591,-72.83 ; 103.483,-72.83 103.483,-52.355 ; 103.483,-31.026 142.591,-31.026 ; 142.591,-72.83 142.591,-31.026
  lines w0.5: -13.829,-81.498 142.571,-81.498 486.297,-81.498 486.297,128.502 -13.829,128.502 -13.829,-81.498
  text "Radio / Oceanography / Laboratory" at 136.644,-45.617 h4
  text "Date" at 16.779,-50.945 h1.76
  text "Modification" at 60.453,-50.945 h1.76
  text "Indice" at 99.422,-50.945 h1.76
  text "Dessine par" at 1.224,-51.027 h1.5
  text ":" at 82.573,-56.956 h1.76
  text "Edition" at 102.512,-56.956 h1.76
  text "CARTE LO-BACKPLANE-2021" at 58.771,-57.598 h1.8
  text "Folio" at 3.373,-62.968 h1.8
  text "Dessinateur" at 102.512,-62.968 h1.76
  text ":" at -5.096,-62.988 h1.76
  text ":" at 82.573,-62.988 h1.76
  text "1/1" at -7.473,-63.364 h1.76
  text "RONVEL" at 79.505,-63.479 h1.95
  text "PLAN DE CABLAGE FACE 4" at 54.771,-64.098 h4
  text ":" at 82.573,-69.582 h1.76
  text "Ind" at 3.373,-69.633 h1.95
  text "Date" at 102.512,-69.633 h1.76
  text "09-06-2021" at 80.471,-70.598 h1.8
Mechanical 7:
  text "PLAN DE CABLAGE FACE 1" at 417.75,-63.875 h4
Mechanical 9:
  text "PLAN DE PERCAGE" at 423.251,-64.026 h4
Drill Drawing:
  drawing of 424 lines, arcs and shapes, not listed
  text "Layer" at 167.839,-10.894 h1.52
  text "Name" at 178.251,-10.894 h1.52
  text "Material" at 202.121,-10.894 h1.52
  text "Thickness" at 223.959,-10.894 h1.52
  text "Constant" at 240.465,-10.894 h1.52
  text "Board Layer Stack" at 254.939,-10.894 h1.52
  text "Symbol" at 4.477,-11.576 h1.83
  text "Count" at 17.326,-11.576 h1.83
  text "Hole Size" at 33.831,-11.576 h1.83
  text "Plated" at 63.287,-11.576 h1.83
  text "Hole Type" at 76.136,-11.576 h1.83
  text "Drill Layer Pair" at 94.774,-11.576 h1.83
  text "Via/Pad" at 124.992,-11.576 h1.83
  text "Pad Shape" at 139.974,-11.576 h1.83
  text "1" at 167.839,-13.942 h1.52
  text "Top Overlay" at 178.251,-13.942 h1.52
  text "1" at 17.326,-15.386 h1.52
  text "0,700mm (27,56mil)" at 33.831,-15.386 h1.52
  text "PTH" at 63.287,-15.386 h1.52
  text "Round" at 76.136,-15.386 h1.52
  text "1 - 4" at 94.774,-15.386 h1.52
  text "Via" at 124.992,-15.386 h1.52
  text "Rounded" at 139.974,-15.386 h1.52
  text "2" at 167.839,-16.99 h1.52
  text "Top Solder" at 178.251,-16.99 h1.52
  text "Solder Resist" at 202.121,-16.99 h1.52
  text "0,020mm" at 223.959,-16.99 h1.52
  text "4" at 240.465,-16.99 h1.52
  text "3" at 17.326,-19.196 h1.52
  text "0,762mm (30,00mil)" at 33.831,-19.196 h1.52
  text "PTH" at 63.287,-19.196 h1.52
  text "Round" at 76.136,-19.196 h1.52
  text "1 - 4" at 94.774,-19.196 h1.52
  text "Pad" at 124.992,-19.196 h1.52
  text "Rounded" at 139.974,-19.196 h1.52
  text "3" at 167.839,-20.038 h1.52
  text "1" at 178.251,-20.038 h1.52
  text "Copper" at 202.121,-20.038 h1.52
  text "0,035mm" at 223.959,-20.038 h1.52
  text "PISTES FACES 1 et 4   / IMPEDANCE 50 OHMS largeur 0.185mm" at 361.375,-22.5 h3.5
  text "6" at 17.326,-23.006 h1.52
  text "0,800mm (31,50mil)" at 33.831,-23.006 h1.52
  text "PTH" at 63.287,-23.006 h1.52
  text "Round" at 76.136,-23.006 h1.52
  text "1 - 4" at 94.774,-23.006 h1.52
  text "Pad" at 124.992,-23.006 h1.52
  text "Rounded" at 139.974,-23.006 h1.52
  text "4" at 167.839,-23.086 h1.52
  text "Dielectric 1" at 178.251,-23.086 h1.52
  text "2116" at 202.121,-23.086 h1.52
  text "0,130mm" at 223.959,-23.086 h1.52
  text "4,45" at 240.465,-23.086 h1.52
  text "MATIERE FR4 / CUIVRE (voir empilage) / SERIGRAPHIE BLANCHE  2 FACES / VERNIS VERT SELECTIF 2 FACES / FINITION NiAu" at 293.875,-25.125 h3.5
  text "5" at 167.839,-26.134 h1.52
  text "Signal Layer 1" at 178.251,-26.134 h1.52
  text "Copper" at 202.121,-26.134 h1.52
  text "0,035mm" at 223.959,-26.134 h1.52
  text "8" at 17.326,-26.816 h1.52
  text "0,914mm (36,00mil)" at 33.831,-26.816 h1.52
  text "PTH" at 63.287,-26.816 h1.52
  text "Round" at 76.136,-26.816 h1.52
  text "1 - 4" at 94.774,-26.816 h1.52
  text "Pad" at 124.992,-26.816 h1.52
  text "(Mixed)" at 139.974,-26.816 h1.52
  text "6" at 167.839,-29.182 h1.52
  text "Dielectric 3" at 178.251,-29.182 h1.52
  text "1,130mm" at 223.959,-29.182 h1.52
  text "4,74" at 240.465,-29.182 h1.52
  text "8" at 17.326,-30.626 h1.52
  text "1,422mm (56,00mil)" at 33.831,-30.626 h1.52
  text "PTH" at 63.287,-30.626 h1.52
  text "Round" at 76.136,-30.626 h1.52
  text "1 - 4" at 94.774,-30.626 h1.52
  text "Pad" at 124.992,-30.626 h1.52
  text "(Mixed)" at 139.974,-30.626 h1.52
  text "7" at 167.839,-32.23 h1.52
  text "Signal Layer 2" at 178.251,-32.23 h1.52
  text "Copper" at 202.121,-32.23 h1.52
  text "0,035mm" at 223.959,-32.23 h1.52
  text "12" at 17.326,-34.436 h1.52
  text "0,508mm (20,00mil)" at 33.831,-34.436 h1.52
  text "PTH" at 63.287,-34.436 h1.52
  text "Round" at 76.136,-34.436 h1.52
  text "1 - 4" at 94.774,-34.436 h1.52
  text "Via" at 124.992,-34.436 h1.52
  text "Rounded" at 139.974,-34.436 h1.52
  text "8" at 167.839,-35.278 h1.52
  text "Dielectric 2" at 178.251,-35.278 h1.52
  text "2116" at 202.121,-35.278 h1.52
  text "0,130mm" at 223.959,-35.278 h1.52
  text "4,45" at 240.465,-35.278 h1.52
  text "12" at 17.326,-38.246 h1.52
  text "3,850mm (151,58mil)" at 33.831,-38.246 h1.52
  text "PTH" at 63.287,-38.246 h1.52
  text "Round" at 76.136,-38.246 h1.52
  text "1 - 4" at 94.774,-38.246 h1.52
  text "Via" at 124.992,-38.246 h1.52
  text "Rounded" at 139.974,-38.246 h1.52
  text "9" at 167.839,-38.326 h1.52
  text "4" at 178.251,-38.326 h1.52
  text "Copper" at 202.121,-38.326 h1.52
  text "0,035mm" at 223.959,-38.326 h1.52
  text "10" at 167.839,-41.374 h1.52
  text "Bottom Solder" at 178.251,-41.374 h1.52
  text "Solder Resist" at 202.121,-41.374 h1.52
  text "0,020mm" at 223.959,-41.374 h1.52
  text "4" at 240.465,-41.374 h1.52
  text "16" at 17.326,-42.056 h1.52
  text "1,400mm (55,12mil)" at 33.831,-42.056 h1.52
  text "PTH" at 63.287,-42.056 h1.52
  text "Round" at 76.136,-42.056 h1.52
  text "1 - 4" at 94.774,-42.056 h1.52
  text "Pad" at 124.992,-42.056 h1.52
  text "Rounded" at 139.974,-42.056 h1.52
  text "11" at 167.839,-44.422 h1.52
  text "Bottom Overlay" at 178.251,-44.422 h1.52
  text "18" at 17.326,-45.866 h1.52
  text "1,100mm (43,31mil)" at 33.831,-45.866 h1.52
  text "PTH" at 63.287,-45.866 h1.52
  text "Round" at 76.136,-45.866 h1.52
  text "1 - 4" at 94.774,-45.866 h1.52
  text "(Mixed)" at 124.992,-45.866 h1.52
  text "Rounded" at 139.974,-45.866 h1.52
  text "68" at 17.326,-49.676 h1.52
  text "1,000mm (39,37mil)" at 33.831,-49.676 h1.52
  text "PTH" at 63.287,-49.676 h1.52
  text "Round" at 76.136,-49.676 h1.52
  text "1 - 4" at 94.774,-49.676 h1.52
  text "(Mixed)" at 124.992,-49.676 h1.52
  text "(Mixed)" at 139.974,-49.676 h1.52
  text "160" at 17.326,-53.486 h1.52
  text "0,965mm (38,00mil)" at 33.831,-53.486 h1.52
  text "PTH" at 63.287,-53.486 h1.52
  text "Round" at 76.136,-53.486 h1.52
  text "1 - 4" at 94.774,-53.486 h1.52
  text "Pad" at 124.992,-53.486 h1.52
  text "(Mixed)" at 139.974,-53.486 h1.52
  text "287" at 17.326,-57.296 h1.52
  text "0,300mm (11,81mil)" at 33.831,-57.296 h1.52
  text "PTH" at 63.287,-57.296 h1.52
  text "Round" at 76.136,-57.296 h1.52
  text "1 - 4" at 94.774,-57.296 h1.52
  text "Via" at 124.992,-57.296 h1.52
  text "Rounded" at 139.974,-57.296 h1.52
  text "7972" at 17.326,-61.106 h1.52
  text "0,350mm (13,78mil)" at 33.831,-61.106 h1.52
  text "PTH" at 63.287,-61.106 h1.52
  text "Round" at 76.136,-61.106 h1.52
  text "1 - 4" at 94.774,-61.106 h1.52
  text "Via" at 124.992,-61.106 h1.52
  text "Rounded" at 139.974,-61.106 h1.52
  text "8571 Total" at 17.326,-64.916 h1.52

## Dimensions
0,101.6 to 469.9,101.6 on Drill Drawing
469.9,101.6 to 469.9,0 on Drill Drawing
